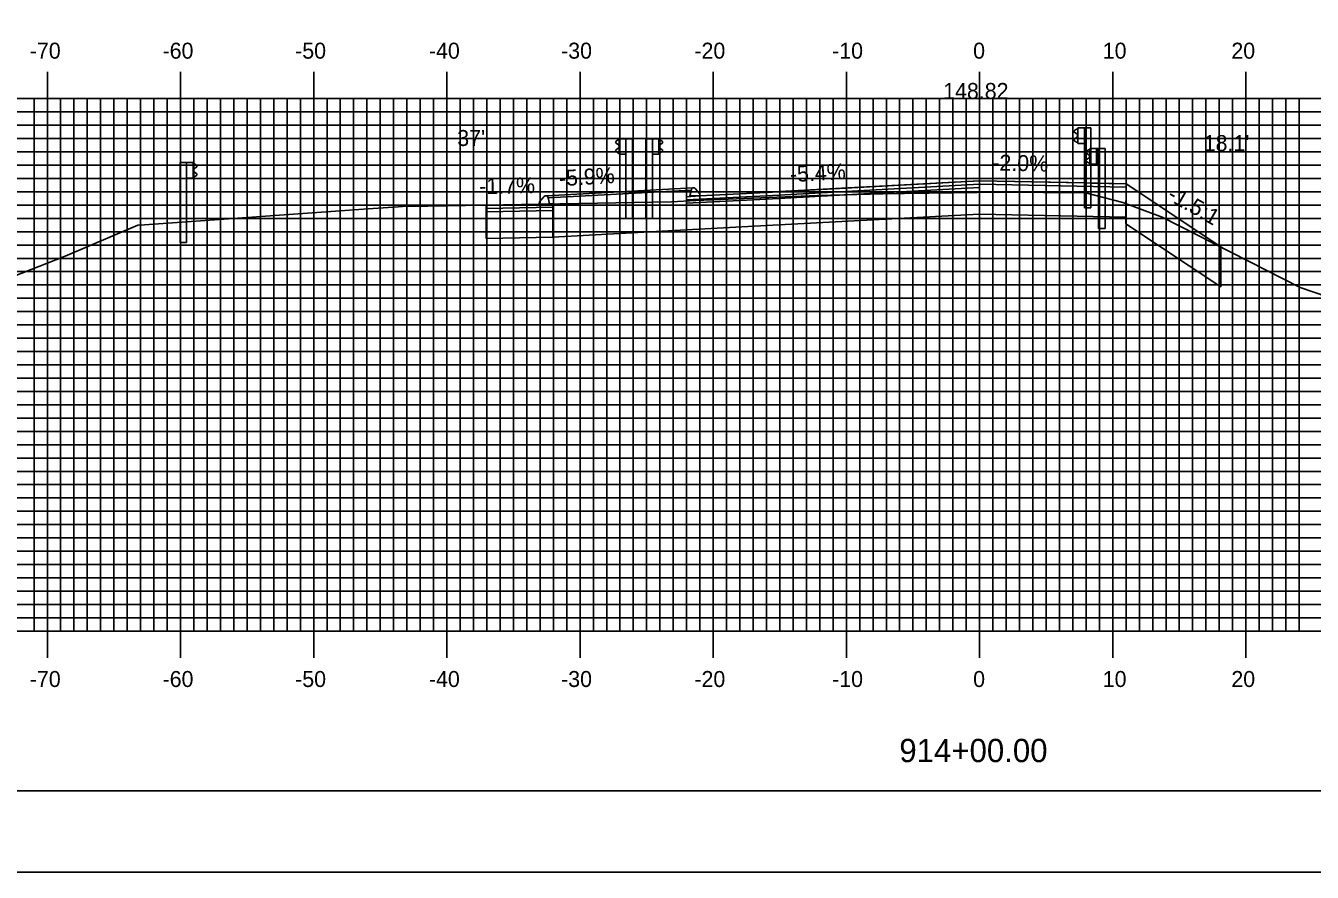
# Model space of a CAD drawing. Extents: x 860652 to 860995, y 364765 to 364985.
# Drawn here: x 860745.8 to 860842.4, y 364765.2 to 364828.8 of the extents above; entities that cross this region are included whole.
import ezdxf

# ---------------------------------------------------------------- set-up
doc = ezdxf.new("R2010")
doc.units = 0
for name, color, linetype in [('ANNOTATION', 7, 'Continuous'), ('BORDER', 7, 'Continuous'), ('D_Curb_Type_3M2_Lt', 7, 'Continuous'), ('D_Curb_Type_3M2_Rt', 7, 'Continuous'), ('D_Guardrail_Beam_Rt', 7, 'Continuous'), ('D_Roadway_Centerline', 7, 'Continuous'), ('D_Roadway_Centerline_Text', 7, 'Continuous'), ('D_Roadway_Edge_Shoulder', 7, 'Continuous'), ('D_Roadway_Edge_TW', 7, 'Continuous'), ('D_Roadway_FinishedGrade', 7, 'Continuous'), ('D_Roadway_Pavement', 7, 'Continuous'), ('D_Roadway_SubGrade', 7, 'Continuous'), ('D_Text_Standard', 7, 'Continuous'), ('H_V ANNOTATION', 7, 'Continuous'), ('M_Guardrail', 7, 'Continuous'), ('M_Roadway_Centerline', 7, 'Continuous'), ('MAJOR', 7, 'Continuous'), ('MINOR', 7, 'Continuous'), ('PATTERNING', 7, 'Continuous'), ('PLOT BOUNDARY', 7, 'Continuous'), ('S_Roadway_Centerline', 7, 'Continuous')]:
    doc.layers.add(name, color=color, linetype=linetype)

msp = doc.modelspace()

# ---------------------------------------------------------------- linework, layer by layer
at = {"layer": 'BORDER'}
msp.add_lwpolyline([(860667.812, 364771.302), (860987.812, 364771.302), (860987.812, 364981.302), (860667.812, 364981.302)], close=True, dxfattribs=at)
at = {"layer": 'D_Curb_Type_3M2_Lt'}
for p, q in [((860795.771, 364816.483), (860795.663, 364815.989)), ((860795.663, 364815.989), (860796.413, 364815.989)), ((860795.907, 364816.612), (860795.911, 364816.612)), ((860796.413, 364816.156), (860796.059, 364816.558)), ((860796.413, 364815.989), (860796.413, 364816.156))]:
    msp.add_line(p, q, dxfattribs=at)
msp.add_arc((860795.934, 364816.448), 0.167, 41.38705, 167.66476, dxfattribs=at)
at = {"layer": 'D_Curb_Type_3M2_Rt'}
for p, q in [((860784.365, 364815.542), (860784.719, 364815.944)), ((860785.007, 364815.869), (860785.115, 364815.375)), ((860784.365, 364815.375), (860784.365, 364815.542)), ((860785.115, 364815.375), (860784.365, 364815.375))]:
    msp.add_line(p, q, dxfattribs=at)
msp.add_arc((860784.844, 364815.834), 0.167, 12.33524, 138.61295, dxfattribs=at)
at = {"layer": 'D_Guardrail_Beam_Rt'}
for p, q in [((860825.593, 364819.442), (860825.45, 364819.342)), ((860825.45, 364819.199), (860825.645, 364819.063)), ((860825.645, 364818.864), (860825.45, 364818.728)), ((860825.683, 364819.463), (860825.609, 364819.449)), ((860825.679, 364818.998), (860825.679, 364818.928)), ((860825.683, 364819.547), (860826.371, 364819.547)), ((860825.683, 364818.38), (860825.683, 364819.547)), ((860826.204, 364819.547), (860826.204, 364818.38)), ((860826.308, 364819.547), (860826.308, 364818.38)), ((860826.371, 364819.547), (860826.841, 364819.547)), ((860826.371, 364819.547), (860826.371, 364818.38)), ((860826.841, 364819.547), (860826.841, 364813.547)), ((860825.45, 364818.584), (860825.593, 364818.485)), ((860825.609, 364818.478), (860825.683, 364818.463)), ((860826.371, 364818.38), (860825.683, 364818.38)), ((860826.35, 364813.547), (860826.35, 364818.38)), ((860826.35, 364813.547), (860826.841, 364813.547))]:
    msp.add_line(p, q, dxfattribs=at)
for centre, major_axis, start_param, end_param in [((860825.5, 364819.27), (-0.0877, 0), 5.323254, 7.243116), ((860825.5, 364818.656), (-0.0877, 0), 5.323254, 7.243116), ((860825.617, 364819.408), (-0.0417, 0), 4.907132, 5.323254), ((860825.6, 364818.998), (0.0789, 0), 0, 0.959931), ((860825.6, 364818.928), (0.0789, 0), 5.323254, 6.283185), ((860825.617, 364818.518), (-0.0417, 0), 0.959931, 1.376053)]:
    msp.add_ellipse(centre, major_axis=major_axis, ratio=0.995501, start_param=start_param, end_param=end_param, dxfattribs=at)
at = {"layer": 'D_Roadway_Centerline'}
for points in [[(860796.413, 364815.989), (860796.418, 364815.99), (860801.412, 364816.259), (860801.449, 364816.261), (860817.412, 364817.123), (860817.429, 364817.123), (860823.923, 364816.993), (860825.411, 364816.963), (860825.412, 364816.963), (860825.794, 364816.956), (860828.412, 364816.903), (860835.52, 364812.165)], [(860780.366, 364815.305), (860780.494, 364815.307), (860784.276, 364815.374), (860784.355, 364815.375), (860784.365, 364815.375)]]:
    msp.add_lwpolyline(points, dxfattribs=at)
at = {"layer": 'D_Roadway_Edge_Shoulder'}
for points in [[(860817.412, 364817.123), (860825.412, 364816.963), (860825.412, 364816.963), (860828.412, 364816.903), (860828.412, 364816.653), (860817.412, 364816.873)], [(860801.412, 364816.259), (860796.413, 364815.989), (860795.413, 364815.935), (860795.413, 364815.685), (860801.412, 364816.009)], [(860780.366, 364815.305), (860784.365, 364815.375), (860785.366, 364815.393), (860785.366, 364815.143), (860780.366, 364815.055)]]:
    msp.add_lwpolyline(points, close=True, dxfattribs=at)
at = {"layer": 'D_Roadway_Edge_TW'}
msp.add_lwpolyline([(860801.412, 364816.259), (860817.412, 364817.123), (860817.412, 364816.873), (860801.412, 364816.009)], close=True, dxfattribs=at)
at = {"layer": 'D_Roadway_FinishedGrade'}
msp.add_line((860828.412, 364816.903), (860828.402, 364813.903), dxfattribs=at)
for points in [[(860828.412, 364816.903), (860829.912, 364815.903), (860835.52, 364812.165)], [(860784.886, 364815.995), (860795.892, 364816.609)], [(860835.52, 364812.165), (860835.52, 364809.165), (860828.402, 364813.903)]]:
    msp.add_lwpolyline(points, dxfattribs=at)
at = {"layer": 'D_Roadway_Pavement'}
for points in [[(860801.412, 364816.009), (860817.412, 364816.873), (860817.412, 364816.623), (860801.412, 364815.759)], [(860801.412, 364816.009), (860795.413, 364815.685), (860795.413, 364815.435), (860801.412, 364815.759)], [(860780.366, 364815.055), (860785.366, 364815.143), (860785.366, 364814.893), (860780.366, 364814.805)]]:
    msp.add_lwpolyline(points, close=True, dxfattribs=at)
msp.add_lwpolyline([(860817.412, 364816.873), (860817.412, 364816.623)], dxfattribs=at)
msp.add_lwpolyline([(860817.412, 364816.873), (860817.412, 364816.623)], dxfattribs=at)
at = {"layer": 'D_Roadway_SubGrade'}
for points in [[(860817.412, 364816.623), (860817.412, 364816.873), (860828.412, 364816.653), (860828.412, 364816.903), (860828.402, 364814.386), (860817.412, 364814.623)], [(860785.366, 364815.393), (860785.366, 364812.893), (860795.413, 364813.435), (860795.413, 364815.435), (860795.413, 364815.685), (860795.413, 364815.935), (860795.654, 364815.948), (860795.76, 364816.435), (860785.015, 364815.835), (860785.112, 364815.389)], [(860801.412, 364815.759), (860795.413, 364815.435), (860795.413, 364815.685), (860795.413, 364813.435), (860801.412, 364813.759)], [(860801.412, 364815.759), (860817.412, 364816.623), (860817.412, 364814.623), (860801.412, 364813.759)], [(860780.366, 364814.805), (860785.366, 364814.893), (860785.366, 364815.143), (860785.366, 364812.893), (860780.366, 364812.805)]]:
    msp.add_lwpolyline(points, close=True, dxfattribs=at)
at = {"layer": 'M_Guardrail'}
for p, q in [((860824.693, 364821.011), (860824.549, 364820.911)), ((860824.549, 364820.768), (860824.745, 364820.632)), ((860824.792, 364821.032), (860824.709, 364821.018)), ((860824.778, 364820.567), (860824.778, 364820.476)), ((860824.792, 364821.105), (860825.281, 364821.105)), ((860824.792, 364819.938), (860824.792, 364821.105)), ((860825.281, 364821.105), (860825.773, 364821.105)), ((860825.281, 364821.105), (860825.281, 364819.938)), ((860825.773, 364821.105), (860825.773, 364815.105)), ((860790.261, 364820.197), (860790.117, 364820.097)), ((860790.117, 364819.953), (860790.312, 364819.817)), ((860790.312, 364819.597), (860790.117, 364819.461)), ((860790.359, 364820.218), (860790.277, 364820.203)), ((860790.346, 364819.753), (860790.346, 364819.662)), ((860790.359, 364820.291), (860790.849, 364820.291)), ((860790.359, 364819.124), (860790.359, 364820.291)), ((860790.849, 364820.291), (860791.341, 364820.291)), ((860790.849, 364820.291), (860790.849, 364819.124)), ((860791.341, 364820.291), (860791.341, 364814.291)), ((860792.357, 364820.289), (860792.357, 364814.289)), ((860792.849, 364820.289), (860792.357, 364820.289)), ((860793.339, 364820.289), (860792.849, 364820.289)), ((860792.849, 364820.289), (860792.849, 364819.122)), ((860793.339, 364819.122), (860793.339, 364820.289)), ((860793.339, 364820.216), (860793.421, 364820.201)), ((860793.352, 364819.751), (860793.352, 364819.66)), ((860793.581, 364819.952), (860793.386, 364819.815)), ((860793.386, 364819.596), (860793.581, 364819.459)), ((860793.437, 364820.195), (860793.581, 364820.095)), ((860824.745, 364820.412), (860824.549, 364820.276)), ((860824.549, 364820.133), (860824.693, 364820.033)), ((860824.709, 364820.026), (860824.792, 364820.011)), ((860825.281, 364819.938), (860824.792, 364819.938)), ((860825.281, 364815.105), (860825.281, 364819.938)), ((860790.117, 364819.318), (860790.261, 364819.218)), ((860790.277, 364819.211), (860790.359, 364819.197)), ((860790.849, 364819.124), (860790.359, 364819.124)), ((860790.849, 364814.291), (860790.849, 364819.124)), ((860792.849, 364814.289), (860792.849, 364819.122)), ((860792.849, 364819.122), (860793.339, 364819.122)), ((860793.421, 364819.209), (860793.339, 364819.195)), ((860793.581, 364819.316), (860793.437, 364819.216)), ((860757.381, 364818.497), (860757.381, 364812.497)), ((860757.873, 364818.497), (860757.381, 364818.497)), ((860758.362, 364818.497), (860757.873, 364818.497)), ((860757.873, 364818.497), (860757.873, 364817.33)), ((860758.362, 364817.33), (860758.362, 364818.497)), ((860758.362, 364818.424), (860758.445, 364818.409)), ((860758.376, 364817.959), (860758.376, 364817.868)), ((860758.605, 364818.159), (860758.409, 364818.023)), ((860758.409, 364817.803), (860758.605, 364817.667)), ((860758.461, 364818.403), (860758.605, 364818.303)), ((860757.873, 364812.497), (860757.873, 364817.33)), ((860757.873, 364817.33), (860758.362, 364817.33)), ((860758.445, 364817.417), (860758.362, 364817.403)), ((860758.605, 364817.524), (860758.461, 364817.424)), ((860825.281, 364815.105), (860825.773, 364815.105)), ((860790.849, 364814.291), (860791.341, 364814.291)), ((860792.849, 364814.289), (860792.357, 364814.289)), ((860757.873, 364812.497), (860757.381, 364812.497))]:
    msp.add_line(p, q, dxfattribs=at)
for centre, major_axis, start_param, end_param in [((860824.6, 364820.839), (-0.0877, 0), 5.323254, 7.243116), ((860824.717, 364820.977), (-0.0417, 0), 4.886922, 5.323254), ((860824.699, 364820.567), (0.0789, 0), 0, 0.959931), ((860790.167, 364820.025), (-0.0877, 0), 5.323254, 7.243116), ((860790.284, 364820.163), (-0.0417, 0), 4.886922, 5.323254), ((860790.267, 364819.753), (0.0789, 0), 0, 0.959931), ((860790.267, 364819.662), (0.0789, 0), 5.323254, 6.283185), ((860793.431, 364819.751), (-0.0789, 0), 5.323254, 6.283185), ((860793.431, 364819.66), (-0.0789, 0), 6.283185, 7.243116), ((860793.414, 364820.161), (0.0417, 0), 0.959931, 1.396263), ((860793.531, 364820.023), (0.0877, 0), 5.323254, 7.243116), ((860824.6, 364820.204), (-0.0877, 0), 5.323254, 7.243116), ((860824.717, 364820.067), (-0.0417, 0), 0.959931, 1.396263), ((860824.699, 364820.476), (0.0789, 0), 5.323254, 6.283185), ((860790.167, 364819.39), (-0.0877, 0), 5.323254, 7.243116), ((860790.284, 364819.252), (-0.0417, 0), 0.959931, 1.396263), ((860793.414, 364819.25), (0.0417, 0), 4.886922, 5.323254), ((860793.531, 364819.388), (0.0877, 0), 5.323254, 7.243116), ((860758.455, 364817.959), (-0.0789, 0), 5.323254, 6.283185), ((860758.455, 364817.868), (-0.0789, 0), 6.283185, 7.243116), ((860758.437, 364818.369), (0.0417, 0), 0.959931, 1.396263), ((860758.554, 364818.231), (0.0877, 0), 5.323254, 7.243116), ((860758.554, 364817.596), (0.0877, 0), 5.323254, 7.243116), ((860758.437, 364817.458), (0.0417, 0), 4.886922, 5.323254)]:
    msp.add_ellipse(centre, major_axis=major_axis, ratio=0.995501, start_param=start_param, end_param=end_param, dxfattribs=at)
at = {"layer": 'MAJOR'}
for p, q in [((860747.412, 364825.306), (860747.412, 364823.302)), ((860757.412, 364825.306), (860757.412, 364823.302)), ((860767.412, 364825.306), (860767.412, 364823.302)), ((860777.412, 364825.306), (860777.412, 364823.302)), ((860787.412, 364825.306), (860787.412, 364823.302)), ((860797.412, 364825.306), (860797.412, 364823.302)), ((860807.412, 364825.306), (860807.412, 364823.302)), ((860817.412, 364825.306), (860817.412, 364823.302)), ((860827.412, 364825.306), (860827.412, 364823.302)), ((860837.412, 364825.306), (860837.412, 364823.302)), ((860677.412, 364823.302), (860957.412, 364823.302)), ((860677.412, 364823.302), (860957.412, 364823.302)), ((860747.412, 364783.302), (860747.412, 364823.302)), ((860757.412, 364783.302), (860757.412, 364823.302)), ((860767.412, 364783.302), (860767.412, 364823.302)), ((860777.412, 364783.302), (860777.412, 364823.302)), ((860787.412, 364783.302), (860787.412, 364823.302)), ((860797.412, 364783.302), (860797.412, 364823.302)), ((860807.412, 364783.302), (860807.412, 364823.302)), ((860817.412, 364783.302), (860817.412, 364823.302)), ((860827.412, 364783.302), (860827.412, 364823.302)), ((860837.412, 364783.302), (860837.412, 364823.302)), ((860677.412, 364818.302), (860957.412, 364818.302)), ((860677.412, 364813.302), (860957.412, 364813.302)), ((860677.412, 364808.302), (860957.412, 364808.302)), ((860677.412, 364803.302), (860957.412, 364803.302)), ((860677.412, 364798.302), (860957.412, 364798.302)), ((860677.412, 364793.302), (860957.412, 364793.302)), ((860677.412, 364788.302), (860957.412, 364788.302)), ((860677.412, 364783.302), (860957.412, 364783.302)), ((860677.412, 364783.302), (860957.412, 364783.302)), ((860747.412, 364781.298), (860747.412, 364783.302)), ((860757.412, 364781.298), (860757.412, 364783.302)), ((860767.412, 364781.298), (860767.412, 364783.302)), ((860777.412, 364781.298), (860777.412, 364783.302)), ((860787.412, 364781.298), (860787.412, 364783.302)), ((860797.412, 364781.298), (860797.412, 364783.302)), ((860807.412, 364781.298), (860807.412, 364783.302)), ((860817.412, 364781.298), (860817.412, 364783.302)), ((860827.412, 364781.298), (860827.412, 364783.302)), ((860837.412, 364781.298), (860837.412, 364783.302))]:
    msp.add_line(p, q, dxfattribs=at)
at = {"layer": 'MINOR'}
for p, q in [((860746.412, 364783.302), (860746.412, 364823.302)), ((860748.412, 364783.302), (860748.412, 364823.302)), ((860749.412, 364783.302), (860749.412, 364823.302)), ((860750.412, 364783.302), (860750.412, 364823.302)), ((860751.412, 364783.302), (860751.412, 364823.302)), ((860752.412, 364783.302), (860752.412, 364823.302)), ((860753.412, 364783.302), (860753.412, 364823.302)), ((860754.412, 364783.302), (860754.412, 364823.302)), ((860755.412, 364783.302), (860755.412, 364823.302)), ((860756.412, 364783.302), (860756.412, 364823.302)), ((860758.412, 364783.302), (860758.412, 364823.302)), ((860759.412, 364783.302), (860759.412, 364823.302)), ((860760.412, 364783.302), (860760.412, 364823.302)), ((860761.412, 364783.302), (860761.412, 364823.302)), ((860762.412, 364783.302), (860762.412, 364823.302)), ((860763.412, 364783.302), (860763.412, 364823.302)), ((860764.412, 364783.302), (860764.412, 364823.302)), ((860765.412, 364783.302), (860765.412, 364823.302)), ((860766.412, 364783.302), (860766.412, 364823.302)), ((860768.412, 364783.302), (860768.412, 364823.302)), ((860769.412, 364783.302), (860769.412, 364823.302)), ((860770.412, 364783.302), (860770.412, 364823.302)), ((860771.412, 364783.302), (860771.412, 364823.302)), ((860772.412, 364783.302), (860772.412, 364823.302)), ((860773.412, 364783.302), (860773.412, 364823.302)), ((860774.412, 364783.302), (860774.412, 364823.302)), ((860775.412, 364783.302), (860775.412, 364823.302)), ((860776.412, 364783.302), (860776.412, 364823.302)), ((860778.412, 364783.302), (860778.412, 364823.302)), ((860779.412, 364783.302), (860779.412, 364823.302)), ((860780.412, 364783.302), (860780.412, 364823.302)), ((860781.412, 364783.302), (860781.412, 364823.302)), ((860782.412, 364783.302), (860782.412, 364823.302)), ((860783.412, 364783.302), (860783.412, 364823.302)), ((860784.412, 364783.302), (860784.412, 364823.302)), ((860785.412, 364783.302), (860785.412, 364823.302)), ((860786.412, 364783.302), (860786.412, 364823.302)), ((860788.412, 364783.302), (860788.412, 364823.302)), ((860789.412, 364783.302), (860789.412, 364823.302)), ((860790.412, 364783.302), (860790.412, 364823.302)), ((860791.412, 364783.302), (860791.412, 364823.302)), ((860792.412, 364783.302), (860792.412, 364823.302)), ((860793.412, 364783.302), (860793.412, 364823.302)), ((860794.412, 364783.302), (860794.412, 364823.302)), ((860795.412, 364783.302), (860795.412, 364823.302)), ((860796.412, 364783.302), (860796.412, 364823.302)), ((860798.412, 364783.302), (860798.412, 364823.302)), ((860799.412, 364783.302), (860799.412, 364823.302)), ((860800.412, 364783.302), (860800.412, 364823.302)), ((860801.412, 364783.302), (860801.412, 364823.302)), ((860802.412, 364783.302), (860802.412, 364823.302)), ((860803.412, 364783.302), (860803.412, 364823.302)), ((860804.412, 364783.302), (860804.412, 364823.302)), ((860805.412, 364783.302), (860805.412, 364823.302)), ((860806.412, 364783.302), (860806.412, 364823.302)), ((860808.412, 364783.302), (860808.412, 364823.302)), ((860809.412, 364783.302), (860809.412, 364823.302)), ((860810.412, 364783.302), (860810.412, 364823.302)), ((860811.412, 364783.302), (860811.412, 364823.302)), ((860812.412, 364783.302), (860812.412, 364823.302)), ((860813.412, 364783.302), (860813.412, 364823.302)), ((860814.412, 364783.302), (860814.412, 364823.302)), ((860815.412, 364783.302), (860815.412, 364823.302)), ((860816.412, 364783.302), (860816.412, 364823.302)), ((860818.412, 364783.302), (860818.412, 364823.302)), ((860819.412, 364783.302), (860819.412, 364823.302)), ((860820.412, 364783.302), (860820.412, 364823.302)), ((860821.412, 364783.302), (860821.412, 364823.302)), ((860822.412, 364783.302), (860822.412, 364823.302)), ((860823.412, 364783.302), (860823.412, 364823.302)), ((860824.412, 364783.302), (860824.412, 364823.302)), ((860825.412, 364783.302), (860825.412, 364823.302)), ((860826.412, 364783.302), (860826.412, 364823.302)), ((860828.412, 364783.302), (860828.412, 364823.302)), ((860829.412, 364783.302), (860829.412, 364823.302)), ((860830.412, 364783.302), (860830.412, 364823.302)), ((860831.412, 364783.302), (860831.412, 364823.302)), ((860832.412, 364783.302), (860832.412, 364823.302)), ((860833.412, 364783.302), (860833.412, 364823.302)), ((860834.412, 364783.302), (860834.412, 364823.302)), ((860835.412, 364783.302), (860835.412, 364823.302)), ((860836.412, 364783.302), (860836.412, 364823.302)), ((860838.412, 364783.302), (860838.412, 364823.302)), ((860839.412, 364783.302), (860839.412, 364823.302)), ((860840.412, 364783.302), (860840.412, 364823.302)), ((860841.412, 364783.302), (860841.412, 364823.302)), ((860677.412, 364822.302), (860957.412, 364822.302)), ((860677.412, 364821.302), (860957.412, 364821.302)), ((860677.412, 364820.302), (860957.412, 364820.302)), ((860677.412, 364819.302), (860957.412, 364819.302)), ((860677.412, 364817.302), (860957.412, 364817.302)), ((860677.412, 364816.302), (860957.412, 364816.302)), ((860677.412, 364815.302), (860957.412, 364815.302)), ((860677.412, 364814.302), (860957.412, 364814.302)), ((860677.412, 364812.302), (860957.412, 364812.302)), ((860677.412, 364811.302), (860957.412, 364811.302)), ((860677.412, 364810.302), (860957.412, 364810.302)), ((860677.412, 364809.302), (860957.412, 364809.302)), ((860677.412, 364807.302), (860957.412, 364807.302)), ((860677.412, 364806.302), (860957.412, 364806.302)), ((860677.412, 364805.302), (860957.412, 364805.302)), ((860677.412, 364804.302), (860957.412, 364804.302)), ((860677.412, 364802.302), (860957.412, 364802.302)), ((860677.412, 364801.302), (860957.412, 364801.302)), ((860677.412, 364800.302), (860957.412, 364800.302)), ((860677.412, 364799.302), (860957.412, 364799.302)), ((860677.412, 364797.302), (860957.412, 364797.302)), ((860677.412, 364796.302), (860957.412, 364796.302)), ((860677.412, 364795.302), (860957.412, 364795.302)), ((860677.412, 364794.302), (860957.412, 364794.302)), ((860677.412, 364792.302), (860957.412, 364792.302)), ((860677.412, 364791.302), (860957.412, 364791.302)), ((860677.412, 364790.302), (860957.412, 364790.302)), ((860677.412, 364789.302), (860957.412, 364789.302)), ((860677.412, 364787.302), (860957.412, 364787.302)), ((860677.412, 364786.302), (860957.412, 364786.302)), ((860677.412, 364785.302), (860957.412, 364785.302)), ((860677.412, 364784.302), (860957.412, 364784.302))]:
    msp.add_line(p, q, dxfattribs=at)
at = {"layer": 'PATTERNING'}
for p, q in [((860828.412, 364816.903), (860828.412, 364816.653)), ((860828.411, 364816.653), (860828.402, 364813.903)), ((860828.412, 364816.653), (860828.411, 364816.653))]:
    msp.add_line(p, q, dxfattribs=at)
for points in [[(860835.52, 364812.165), (860829.912, 364815.903), (860828.412, 364816.903), (860828.412, 364816.903)], [(860828.402, 364813.903), (860835.52, 364809.165), (860835.52, 364812.165)]]:
    msp.add_lwpolyline(points, dxfattribs=at)
at = {"layer": 'PLOT BOUNDARY'}
msp.add_lwpolyline([(860651.626, 364765.184), (860991.626, 364765.184), (860991.626, 364985.184), (860651.626, 364985.184)], close=True, dxfattribs=at)
at = {"layer": 'S_Roadway_Centerline'}
msp.add_lwpolyline([(860736.991, 364806.864), (860748.76, 364811.462), (860754.216, 364813.794), (860754.701, 364813.813), (860771.514, 364815.018), (860773.746, 364815.178), (860773.855, 364815.191), (860774.084, 364815.202), (860775.974, 364815.229), (860787.325, 364815.427), (860794.274, 364815.555), (860796.116, 364815.641), (860805.246, 364816.027), (860811.171, 364816.175), (860811.784, 364816.181), (860819.055, 364816.279), (860825.364, 364816.235), (860828.158, 364815.505), (860831.129, 364814.406), (860841.479, 364809.123), (860849.632, 364806.324)], dxfattribs=at)

# ---------------------------------------------------------------- texts
at = {"layer": 'ANNOTATION'}
for s, rotation, p in [('-2.0%', 358.85433, (860818.362, 364817.905)), ('-5.9%', 3.36715, (860785.86, 364816.714)), ('-5.4%', 3.09099, (860803.203, 364817.024)), ('-1.7%', 1.0025, (860779.85, 364816.125)), ('-1.5:1', 330.177, (860831.422, 364815.772))]:
    msp.add_text(s, height=1.2, rotation=rotation, dxfattribs=at).set_placement(p)
at = {"layer": 'D_Roadway_Centerline_Text'}
msp.add_text('148.82', height=1.2, dxfattribs=at).set_placement((860814.678, 364823.274))
at = {"layer": 'D_Text_Standard'}
for s, p in [("37'", (860778.191, 364819.742)), ("18.1'", (860834.243, 364819.361))]:
    msp.add_text(s, height=1.2, dxfattribs=at).set_placement(p)
at = {"layer": 'H_V ANNOTATION'}
for s, height, p in [('-70', 1.2, (860746.096, 364826.302)), ('-60', 1.2, (860756.064, 364826.302)), ('-50', 1.2, (860766.021, 364826.302)), ('-40', 1.2, (860776.064, 364826.302)), ('-30', 1.2, (860785.989, 364826.302)), ('-20', 1.2, (860795.999, 364826.302)), ('-10', 1.2, (860806.342, 364826.302)), ('0', 1.2, (860816.931, 364826.302)), ('10', 1.2, (860826.663, 364826.302)), ('20', 1.2, (860836.32, 364826.302)), ('-70', 1.2, (860746.096, 364779.102)), ('-60', 1.2, (860756.064, 364779.102)), ('-50', 1.2, (860766.021, 364779.102)), ('-40', 1.2, (860776.064, 364779.102)), ('-30', 1.2, (860785.989, 364779.102)), ('-20', 1.2, (860795.999, 364779.102)), ('-10', 1.2, (860806.342, 364779.102)), ('0', 1.2, (860816.931, 364779.102)), ('10', 1.2, (860826.663, 364779.102)), ('20', 1.2, (860836.32, 364779.102)), ('914+00.00', 1.75, (860811.389, 364773.458))]:
    msp.add_text(s, height=height, dxfattribs=at).set_placement(p)
at = {"layer": 'M_Roadway_Centerline'}
for s, p in [('C', (860805.24, 364816.027)), ('L', (860805.246, 364816.019)), ('C', (860773.85, 364815.191)), ('L', (860773.855, 364815.183))]:
    msp.add_text(s, height=0.0146, dxfattribs=at).set_placement(p)

doc.saveas('drawing.dxf')
